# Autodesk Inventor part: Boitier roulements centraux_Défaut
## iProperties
Shininess: 64.0
Length Units: 11269
Angle Units: 11279
Time Units: 11290
Mass Units: 11283
Length Display Precision: 3
Angle Display Precision: 2
Compacted: True
Part Number: Boitier roulements centraux_Défaut
Document SubType Name: Modeling
Created: 2006-01
Material: Par défaut
Designer: riri
Density: 0.0
Volumn: 0.0
Area: 0.0
PropertySet Name: Model Information
Control State: 0
Master: False
Checked Out: False
Author: riri
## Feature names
1. Base1
